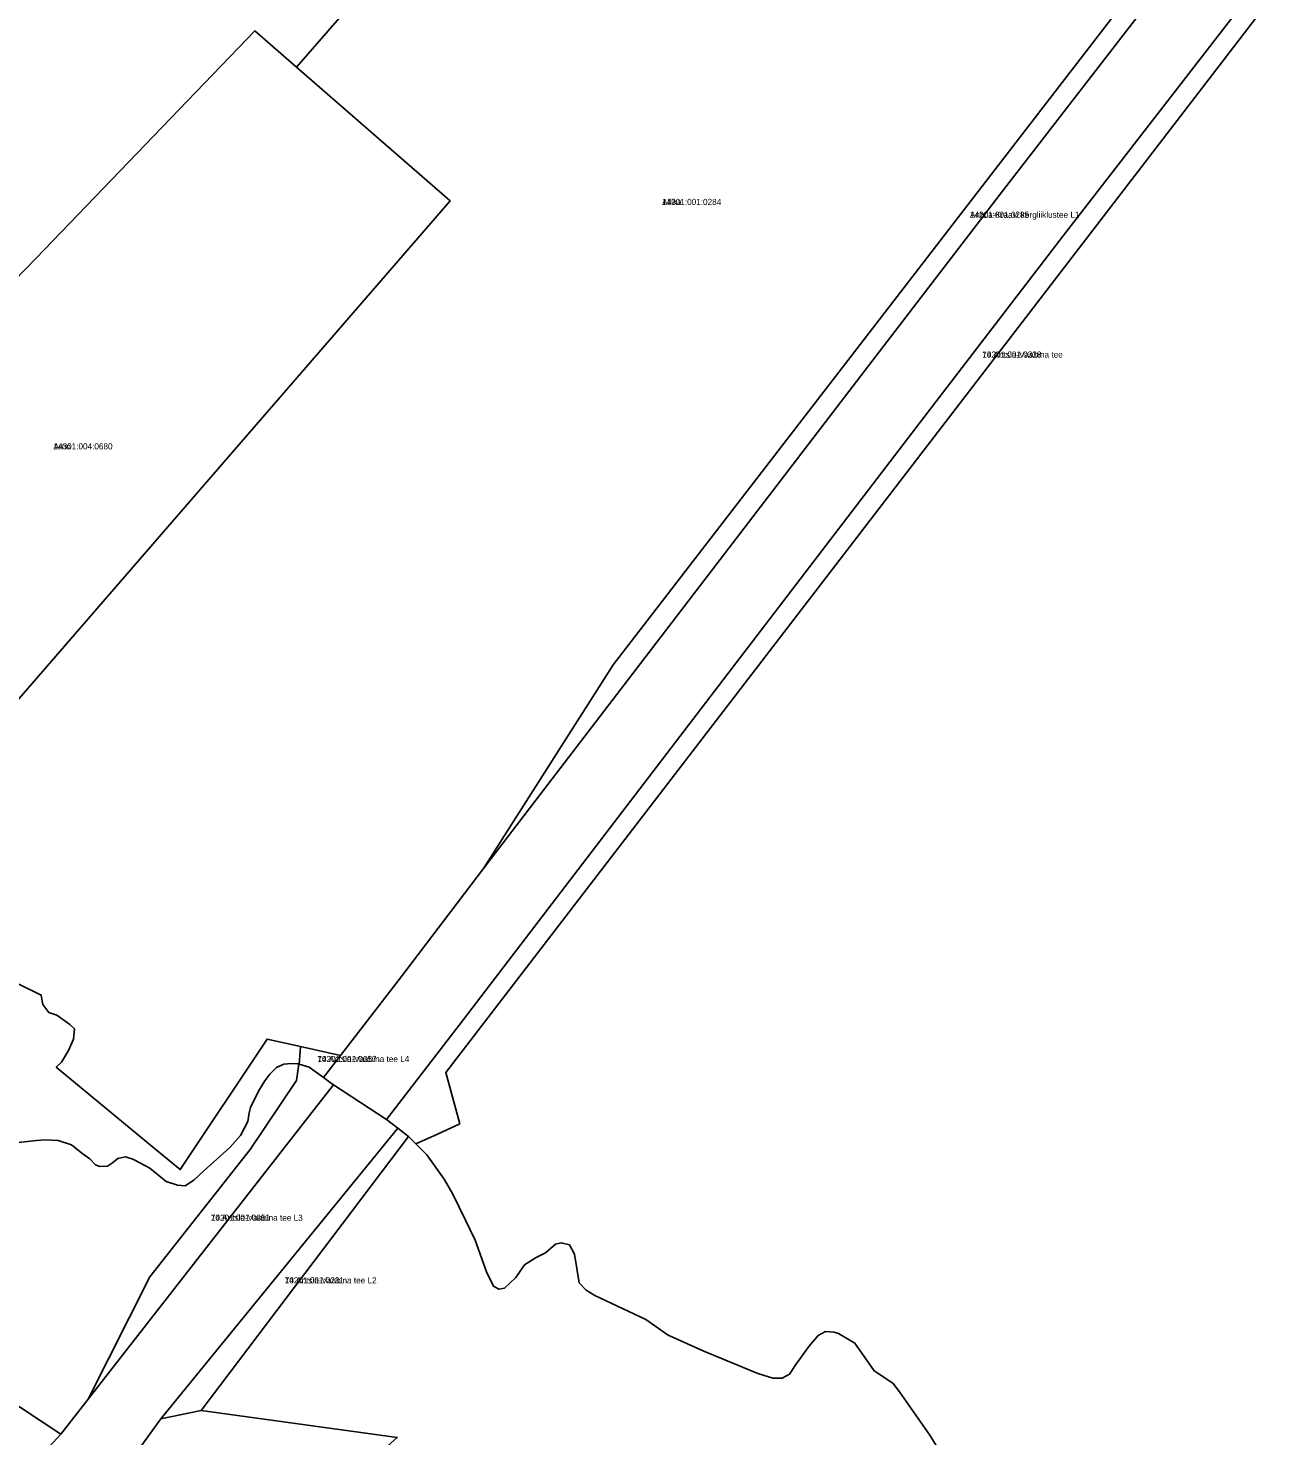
# Model space of a CAD drawing. Extents: x 640657 to 665127, y 6395726 to 6426831.
# Drawn here: x 650809.6 to 651118.5, y 6413060.8 to 6413405.9 of the extents above; entities that cross this region are included whole.
import ezdxf

# ---------------------------------------------------------------- set-up
doc = ezdxf.new("R2010")
doc.units = 0
for name, color, linetype in [('L_AADRESS', 7, 'Continuous'), ('PIIR', 7, 'Continuous'), ('TUNNUS', 7, 'Continuous')]:
    doc.layers.add(name, color=color, linetype=linetype)

msp = doc.modelspace()

# ---------------------------------------------------------------- linework, layer by layer
at = {"layer": 'PIIR'}
for points in [[(650960.7, 6413586.3), (651020.47, 6413562.79), (650934.78, 6413464.58), (650875.39, 6413396.42), (650865.22, 6413405.29), (650811.5, 6413349.45), (650721.48, 6413256.75), (650718.51, 6413253.84), (650695.62, 6413281.58), (650699.97, 6413286.8), (650779.67, 6413380.59), (650833.36, 6413441.9)], [(651184.91, 6413512.64), (651189.65, 6413511.4), (650911.99, 6413149.85), (650915.43, 6413137.26), (650909.95, 6413134.76), (650904.68, 6413132.36), (650902.87, 6413134.19), (650900.25, 6413136.22), (650897.48, 6413138.36), (650915.26, 6413161.45), (650971.53, 6413235.07), (651028.45, 6413309.41), (651063.42, 6413355.04), (651126.29, 6413436.36), (651177.63, 6413503.09)], [(650956.84, 6413246.3), (650921.28, 6413199.88), (650953.08, 6413249.81), (651155.07, 6413511.93), (651158.79, 6413510.55), (651159.77, 6413510.14), (651111.64, 6413447.66), (651048.76, 6413366.33), (651013.76, 6413320.66)], [(650775.04, 6413204.04), (650765.99, 6413213.47), (650756.47, 6413224.03), (650746.95, 6413231.53), (650736.17, 6413238.06), (650727.6, 6413243.95), (650718.51, 6413253.84), (650721.48, 6413256.75), (650811.5, 6413349.45), (650865.22, 6413405.29), (650875.39, 6413396.42), (650913.12, 6413363.57), (650777.7, 6413207.45)], [(650639.81, 6413174.35), (650661.38, 6413159.66), (650687.87, 6413141.56), (650726.69, 6413115.56), (650728.32, 6413120.2), (650817.6, 6413061.15), (650809.09, 6413051.96), (650774.49, 6413073.67), (650757.49, 6413085.02), (650736.91, 6413098.43), (650728.56, 6413104.06), (650707.39, 6413117.67), (650694.6, 6413126.1), (650690.86, 6413128.47), (650674.2, 6413139.68), (650668.91, 6413143.29), (650635.45, 6413166.68)], [(650876.37, 6413156.25), (650886.18, 6413154.04), (650882.02, 6413148.61), (650878.53, 6413151.17), (650876.08, 6413151.88), (650876.28, 6413154.99)], [(650875.73, 6413150.17), (650875.98, 6413151.91), (650876.08, 6413151.88), (650878.53, 6413151.17), (650882.02, 6413148.61), (650883.68, 6413147.4), (650884.47, 6413146.87), (650879.77, 6413140.76), (650824.33, 6413069.75), (650839.45, 6413099.8), (650864.04, 6413131.02), (650875.39, 6413147.9)], [(650900.25, 6413136.22), (650902.87, 6413134.19), (650852, 6413067.01), (650842.18, 6413064.93)], [(650828.73, 6413046.43), (650842.18, 6413064.93), (650852, 6413067.01), (650900.11, 6413060.4), (650875.35, 6413038.19), (650853.19, 6413018.67)]]:
    msp.add_lwpolyline(points, close=True, dxfattribs=at)
for points in [[(651155.07, 6413511.93), (650953.08, 6413249.81), (650921.28, 6413199.88), (650900.58, 6413172.71), (650886.18, 6413154.04), (650876.37, 6413156.25), (650868.18, 6413158.08), (650846.89, 6413126.07), (650841, 6413130.94), (650816.51, 6413151.19), (650817.79, 6413152.38), (650819.52, 6413155.28), (650820.72, 6413158.05), (650820.99, 6413160.57), (650819.81, 6413161.63), (650816.64, 6413163.89), (650814.66, 6413164.56), (650813.21, 6413166.55), (650813.08, 6413167.34), (650812.82, 6413168.84), (650807.32, 6413171.55)], [(651126.29, 6413436.36), (651063.42, 6413355.04), (651028.45, 6413309.41), (650971.53, 6413235.07), (650915.26, 6413161.45), (650897.48, 6413138.36), (650884.47, 6413146.87), (650883.68, 6413147.4), (650882.02, 6413148.61), (650886.18, 6413154.04), (650900.58, 6413172.71), (650921.28, 6413199.88), (650956.84, 6413246.3), (651013.76, 6413320.66), (651048.76, 6413366.33), (651111.64, 6413447.66), (651159.77, 6413510.14)], [(651034.94, 6413053.96), (651030.69, 6413060.95), (651023.29, 6413071.57), (651021.65, 6413073.68), (651017.09, 6413076.72), (651012.31, 6413083.54), (651008.33, 6413085.9), (651007.24, 6413086.18), (651005.13, 6413086.37), (651003.3, 6413085.37), (651001, 6413082.72), (650997.87, 6413078.25), (650996.31, 6413075.88), (650994.47, 6413074.88), (650992.19, 6413074.88), (650988.53, 6413076.09), (650976.3, 6413081.12), (650975.28, 6413081.54), (650966.51, 6413085.5), (650961.03, 6413089.34), (650948.52, 6413095.18), (650946.42, 6413096.46), (650944.68, 6413098.3), (650944.15, 6413101.78), (650943.61, 6413105.35), (650942.32, 6413107.6), (650940.32, 6413108.11), (650938.95, 6413107.75), (650936.47, 6413105.65), (650934.18, 6413104.47), (650931.34, 6413102.74), (650929.22, 6413099.64), (650926.37, 6413097), (650925, 6413096.73), (650923.72, 6413097.46), (650921.98, 6413100.96), (650919.2, 6413108.79), (650916.87, 6413113.65), (650913.74, 6413120.01), (650911.59, 6413123.68), (650907.39, 6413129.64), (650904.68, 6413132.36), (650909.95, 6413134.76), (650915.43, 6413137.26), (650911.99, 6413149.85), (651189.65, 6413511.4)], [(650777.7, 6413207.45), (650913.12, 6413363.57), (650875.39, 6413396.42), (650934.78, 6413464.58)], [(650807.32, 6413171.55), (650812.82, 6413168.84), (650813.08, 6413167.34), (650813.21, 6413166.55), (650814.66, 6413164.56), (650816.64, 6413163.89), (650819.81, 6413161.63), (650820.99, 6413160.57), (650820.72, 6413158.05), (650819.52, 6413155.28), (650817.79, 6413152.38), (650816.51, 6413151.19), (650841, 6413130.94), (650846.89, 6413126.07), (650868.18, 6413158.08), (650876.37, 6413156.25), (650876.28, 6413154.99), (650876.08, 6413151.88), (650875.98, 6413151.91), (650875.72, 6413151.98), (650874.06, 6413152.1), (650872.34, 6413151.94), (650870.51, 6413151.12), (650868.84, 6413149.46), (650867.67, 6413147.8), (650866.05, 6413145.26), (650864.09, 6413141.31), (650863.82, 6413139.95), (650863.48, 6413137.85), (650861.64, 6413134.42), (650859.02, 6413131.44), (650852.63, 6413125.64), (650850.24, 6413123.44), (650848.08, 6413122.11), (650846.19, 6413122.23), (650843.48, 6413123.13), (650839.42, 6413126.44), (650837.02, 6413127.7), (650835.3, 6413128.63), (650833.45, 6413129.17), (650831.6, 6413128.78), (650830.27, 6413127.72), (650829.08, 6413126.94), (650827.22, 6413126.81), (650826.16, 6413127.21), (650824.72, 6413128.67), (650822.74, 6413130.13), (650820.23, 6413132.13), (650816.93, 6413133.2), (650813.88, 6413133.34), (650811.64, 6413133.22), (650807.27, 6413132.7)], [(650807.27, 6413132.7), (650811.64, 6413133.22), (650813.88, 6413133.34), (650816.93, 6413133.2), (650820.23, 6413132.13), (650822.74, 6413130.13), (650824.72, 6413128.67), (650826.16, 6413127.21), (650827.22, 6413126.81), (650829.08, 6413126.94), (650830.27, 6413127.72), (650831.6, 6413128.78), (650833.45, 6413129.17), (650835.3, 6413128.63), (650837.02, 6413127.7), (650839.42, 6413126.44), (650843.48, 6413123.13), (650846.19, 6413122.23), (650848.08, 6413122.11), (650850.24, 6413123.44), (650852.63, 6413125.64), (650859.02, 6413131.44), (650861.64, 6413134.42), (650863.48, 6413137.85), (650863.82, 6413139.95), (650864.09, 6413141.31), (650866.05, 6413145.26), (650867.67, 6413147.8), (650868.84, 6413149.46), (650870.51, 6413151.12), (650872.34, 6413151.94), (650874.06, 6413152.1), (650875.72, 6413151.98), (650875.98, 6413151.91), (650875.73, 6413150.17), (650875.39, 6413147.9), (650864.04, 6413131.02), (650839.45, 6413099.8), (650824.33, 6413069.75), (650817.6, 6413061.15), (650728.32, 6413120.2)], [(650809.09, 6413051.96), (650817.6, 6413061.15), (650824.33, 6413069.75), (650879.77, 6413140.76), (650884.47, 6413146.87), (650897.48, 6413138.36), (650900.25, 6413136.22), (650842.18, 6413064.93), (650828.73, 6413046.43), (650822.51, 6413038.14), (650817.7, 6413031.91), (650806.76, 6413017.69)], [(650900.11, 6413060.4), (650852, 6413067.01), (650902.87, 6413134.19), (650904.68, 6413132.36), (650907.39, 6413129.64), (650911.59, 6413123.68), (650913.74, 6413120.01), (650916.87, 6413113.65), (650919.2, 6413108.79), (650921.98, 6413100.96), (650923.72, 6413097.46), (650925, 6413096.73), (650926.37, 6413097), (650929.22, 6413099.64), (650931.34, 6413102.74), (650934.18, 6413104.47), (650936.47, 6413105.65), (650938.95, 6413107.75), (650940.32, 6413108.11), (650942.32, 6413107.6), (650943.61, 6413105.35), (650944.15, 6413101.78), (650944.68, 6413098.3), (650946.42, 6413096.46), (650948.52, 6413095.18), (650961.03, 6413089.34), (650966.51, 6413085.5), (650975.28, 6413081.54), (650976.3, 6413081.12), (650988.53, 6413076.09), (650992.19, 6413074.88), (650994.47, 6413074.88), (650996.31, 6413075.88), (650997.87, 6413078.25), (651001, 6413082.72), (651003.3, 6413085.37), (651005.13, 6413086.37), (651007.24, 6413086.18), (651008.33, 6413085.9), (651012.31, 6413083.54), (651017.09, 6413076.72), (651021.65, 6413073.68), (651023.29, 6413071.57), (651030.69, 6413060.95), (651034.94, 6413053.96)]]:
    msp.add_lwpolyline(points, dxfattribs=at)

# ---------------------------------------------------------------- texts
at = {"layer": 'L_AADRESS'}
for s, p in [('Allika', (650965.05, 6413362.59)), ('Antsla-Kraavi kergliiklustee L1', (651040.53, 6413359.44)), ('70 Antsla-Vaabina tee', (651043.56, 6413325.16)), ('Arno', (650815.81, 6413302.66)), ('70 Antsla-Vaabina tee L4', (650880.53, 6413152.43)), ('70 Antsla-Vaabina tee L3', (650854.4, 6413113.52)), ('70 Antsla-Vaabina tee L2', (650872.52, 6413098.15))]:
    msp.add_text(s, height=1.5, dxfattribs=at).set_placement(p)
at = {"layer": 'TUNNUS'}
for s, p in [('14201:001:0284', (650965.05, 6413362.59)), ('14201:001:0285', (651040.53, 6413359.44)), ('14201:001:0338', (651043.56, 6413325.16)), ('14301:004:0680', (650815.81, 6413302.66)), ('14201:001:0657', (650880.53, 6413152.43)), ('14201:001:0651', (650854.4, 6413113.52)), ('14201:001:0231', (650872.52, 6413098.15))]:
    msp.add_text(s, height=1.5, dxfattribs=at).set_placement(p)

doc.saveas('drawing.dxf')
